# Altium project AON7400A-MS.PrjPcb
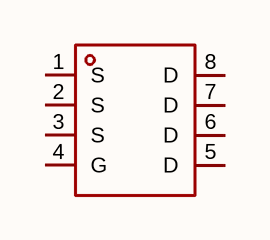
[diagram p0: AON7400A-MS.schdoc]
1 sheet, 1 parts. Net scope: global (net labels, ports and power ports of the same name join across sheets).

## Sheet AON7400A-MS.schdoc
size 127 x 101 mm

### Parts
Q?  aon7400a-ms  [POWERPAK-1212-8_L3.0-W3.0-P0.65-LS3.3-BL]  (value not drawn)

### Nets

Not connected (* = marked no-connect by the designer): Q? 1(S) 2(S) 3(S) 4(G) 5(D) 6(D) 7(D) 8(D)

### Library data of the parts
Q? = aon7400a-ms: 数量:1个N沟道;漏源电压(Vdss):30V;连续漏极电流(Id):35A;导通电阻(RDS(on)):7.5mΩ@10V;耗散功率(Pd):37.5W;阈值电压(Vgs(th)):1.2V;; Manufacturer: MSKSEMI(美森科); AddInBom: yes; ModelId: 74fc8db97a8d4d328d7f3b4acba39a5e; ModelTransform: 129.921,129.921,0,0,0,0,0,0,0; Number: 1个N沟道; Drain to Source Voltage: 30V; Current - Continuous Drain(Id): 35A; Pd - Power Dissipation: 37.5W; Gate Threshold Voltage (Vgs(th)): 1.2V; Gate Charge(Qg): 9.8nC; Input Capacitance(Ciss): 940pF; Reverse Transfer Capacitance (Crss@Vds): 109pF; Type: N沟道; Output Capacitance(Coss): 131pF; Vgs: ±20V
